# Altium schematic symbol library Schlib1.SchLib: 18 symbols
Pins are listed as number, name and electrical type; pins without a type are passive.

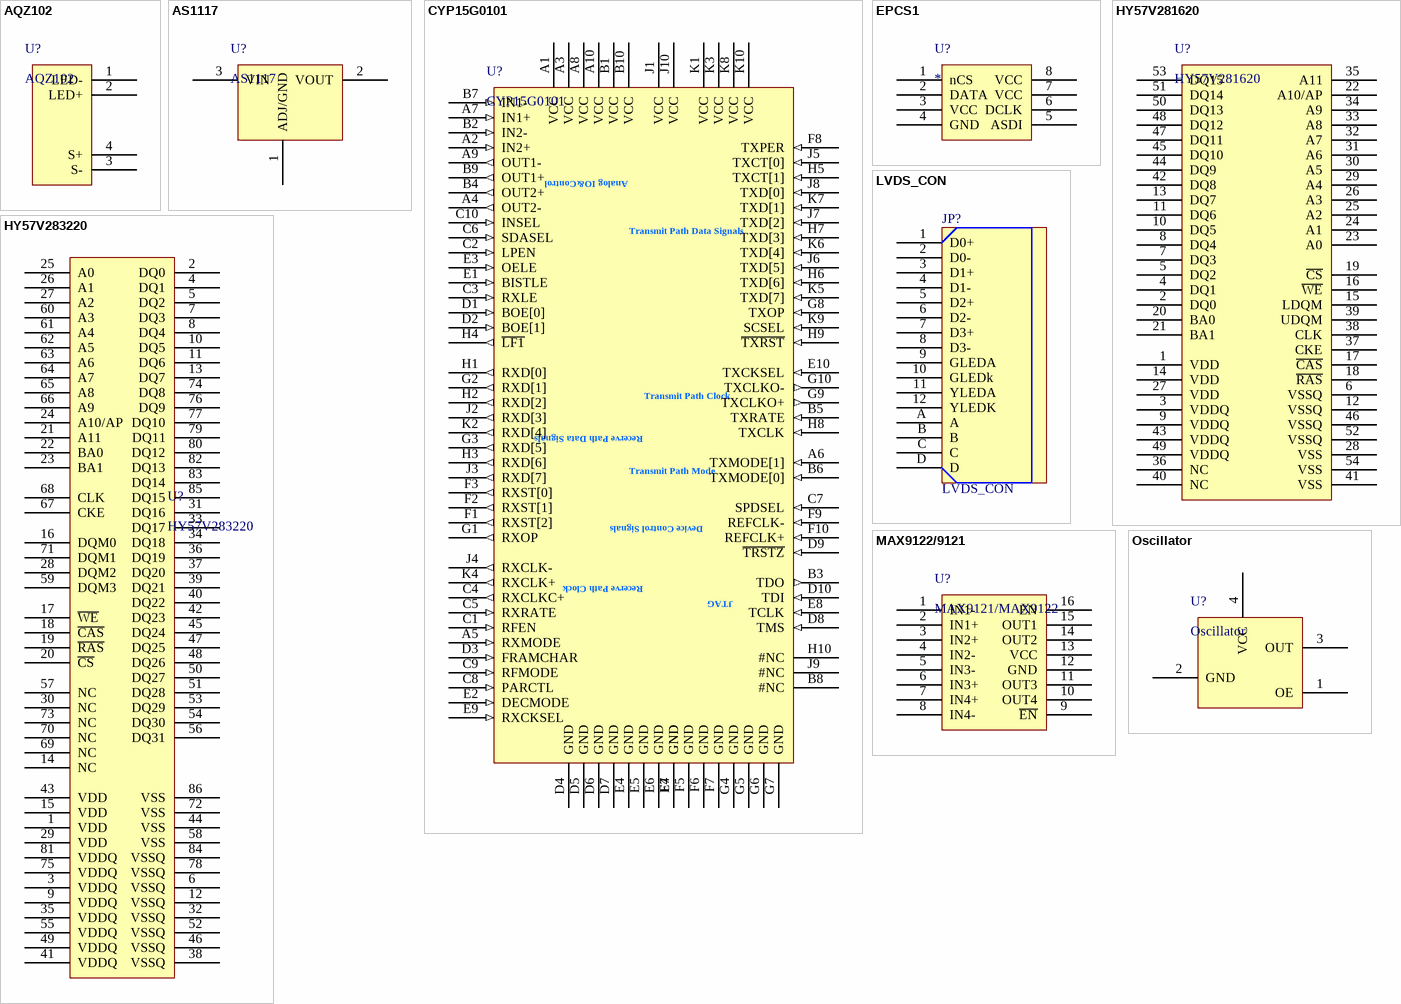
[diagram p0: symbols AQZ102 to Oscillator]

## AQZ102
designator U?
footprint AQZ102
pins: 1 LED-, 2 LED+, 3 S-, 4 S+

## AS1117
designator U?
footprint LM1117
pins: 1 ADJ/GND, 2 VOUT, 3 VIN

## CYP15G0101
designator U?
Hotlink II
footprint BGA100x10 (for CYP15G0101)
pins: A1 VCC, A2 IN2+ (in), A3 VCC, A4 OUT2- (out), A5 RXMODE (in), A6 TXMODE[1] (in), A7 IN1+ (in), A8 VCC, A9 OUT1- (out), A10 VCC, B1 VCC, B2 IN2- (in), B3 TDO (out), B4 OUT2+ (out), B5 TXRATE (in), B6 TXMODE[0] (in), B7 IN1- (in), B8 #NC, B9 OUT1+ (out), B10 VCC, C1 RFEN (in), C2 LPEN (in), C3 RXLE (in), C4 RXCLKC+ (out), C5 RXRATE (in), C6 SDASEL (in), C7 SPDSEL (in), C8 PARCTL (in), C9 RFMODE (in), C10 INSEL (in), D1 BOE[0] (in), D2 BOE[1] (in), D3 FRAMCHAR (in), D4 GND, D5 GND, D6 GND, D7 GND, D8 TMS (in), D9 ~{TRSTZ} (in), D10 TDI (in), E1 BISTLE (in), E2 DECMODE (in), E3 OELE (in), E4 GND, E5 GND, E6 GND, E7 GND, E8 TCLK (in), E9 RXCKSEL (in), E10 TXCKSEL (in), F1 RXST[2] (out), F2 RXST[1] (out), F3 RXST[0] (out), F4 GND, F5 GND, F6 GND, F7 GND, F8 TXPER (in), F9 REFCLK- (in), F10 REFCLK+ (in), G1 RXOP (out), G2 RXD[1] (out), G3 RXD[5] (out), G4 GND, G5 GND, G6 GND, G7 GND, G8 TXOP (in), G9 TXCLKO+ (out), G10 TXCLKO- (out), H1 RXD[0] (out), H2 RXD[2] (out), H3 RXD[6] (out), H4 ~{LF1} (out), H5 TXCT[1] (in), H6 TXD[6] (in), H7 TXD[3] (in), H8 TXCLK (in), H9 ~{TXRST} (in), H10 #NC, J1 VCC, J2 RXD[3] (out), J3 RXD[7] (out), J4 RXCLK- (out), J5 TXCT[0] (in), J6 TXD[5] (in), J7 TXD[2] (in), J8 TXD[0] (in), J9 #NC, J10 VCC, K1 VCC, K2 RXD[4] (out), K3 VCC, K4 RXCLK+ (out), K5 TXD[7] (in), K6 TXD[4] (in), K7 TXD[1] (in), K8 VCC, K9 SCSEL (in), K10 VCC

## EPCS1
designator U?
footprint Model Name (Footprint not found)
pins: 1 nCS, 2 DATA, 3 VCC, 4 GND, 5 ASDI, 6 DCLK, 7 VCC, 8 VCC

## HY57V281620
designator U?
footprint TSOP-54
pins: 1 VDD, 2 DQ0, 3 VDDQ, 4 DQ1, 5 DQ2, 6 VSSQ, 7 DQ3, 8 DQ4, 9 VDDQ, 10 DQ5, 11 DQ6, 12 VSSQ, 13 DQ7, 14 VDD, 15 LDQM, 16 ~{WE}, 17 ~{CAS}, 18 ~{RAS}, 19 ~{CS}, 20 BA0, 21 BA1, 22 A10/AP, 23 A0, 24 A1, 25 A2, 26 A3, 27 VDD, 28 VSS, 29 A4, 30 A5, 31 A6, 32 A7, 33 A8, 34 A9, 35 A11, 36 NC, 37 CKE, 38 CLK, 39 UDQM, 40 NC, 41 VSS, 42 DQ8, 43 VDDQ, 44 DQ9, 45 DQ10, 46 VSSQ, 47 DQ11, 48 DQ12, 49 VDDQ, 50 DQ13, 51 DQ14, 52 VSSQ, 53 DQ15, 54 VSS

## HY57V283220
designator U?
by TX
footprint TSOP86
pins: 1 VDD, 2 DQ0, 3 VDDQ, 4 DQ1, 5 DQ2, 6 VSSQ, 7 DQ3, 8 DQ4, 9 VDDQ, 10 DQ5, 11 DQ6, 12 VSSQ, 13 DQ7, 14 NC, 15 VDD, 16 DQM0, 17 ~{WE}, 18 ~{CAS}, 19 ~{RAS}, 20 ~{CS}, 21 A11, 22 BA0, 23 BA1, 24 A10/AP, 25 A0, 26 A1, 27 A2, 28 DQM2, 29 VDD, 30 NC, 31 DQ16, 32 VSSQ, 33 DQ17, 34 DQ18, 35 VDDQ, 36 DQ19, 37 DQ20, 38 VSSQ, 39 DQ21, 40 DQ22, 41 VDDQ, 42 DQ23, 43 VDD, 44 VSS, 45 DQ24, 46 VSSQ, 47 DQ25, 48 DQ26, 49 VDDQ, 50 DQ27, 51 DQ28, 52 VSSQ, 53 DQ29, 54 DQ30, 55 VDDQ, 56 DQ31, 57 NC, 58 VSS, 59 DQM3, 60 A3, 61 A4, 62 A5, 63 A6, 64 A7, 65 A8, 66 A9, 67 CKE, 68 CLK, 69 NC, 70 NC, 71 DQM1, 72 VSS, 73 NC, 74 DQ8, 75 VDDQ, 76 DQ9, 77 DQ10, 78 VSSQ, 79 DQ11, 80 DQ12, 81 VDDQ, 82 DQ13, 83 DQ14, 84 VSSQ, 85 DQ15, 86 VSS

## LVDS_CON
designator JP?
footprint HR911103A
pins: 1 D0+, 2 D0-, 3 D1+, 4 D1-, 5 D2+, 6 D2-, 7 D3+, 8 D3-, 9 GLEDA, 10 GLEDk, 11 YLEDA, 12 YLEDK, A, B, C, D

## MAX9122/9121
designator U?, comment MAX9121/MAX9122
footprint SOIC12 (for MAX9122/9121)
footprint SOP16 (for MAX9122)
pins: 1 IN1-, 2 IN1+, 3 IN2+, 4 IN2-, 5 IN3-, 6 IN3+, 7 IN4+, 8 IN4-, 9 ~{EN}, 10 OUT4, 11 OUT3, 12 GND, 13 VCC, 14 OUT2, 15 OUT1, 16 EN

## Oscillator
designator U?
footprint OSC50MHz (for 50MHz)
pins: 1 OE, 2 GND, 3 OUT, 4 VCC

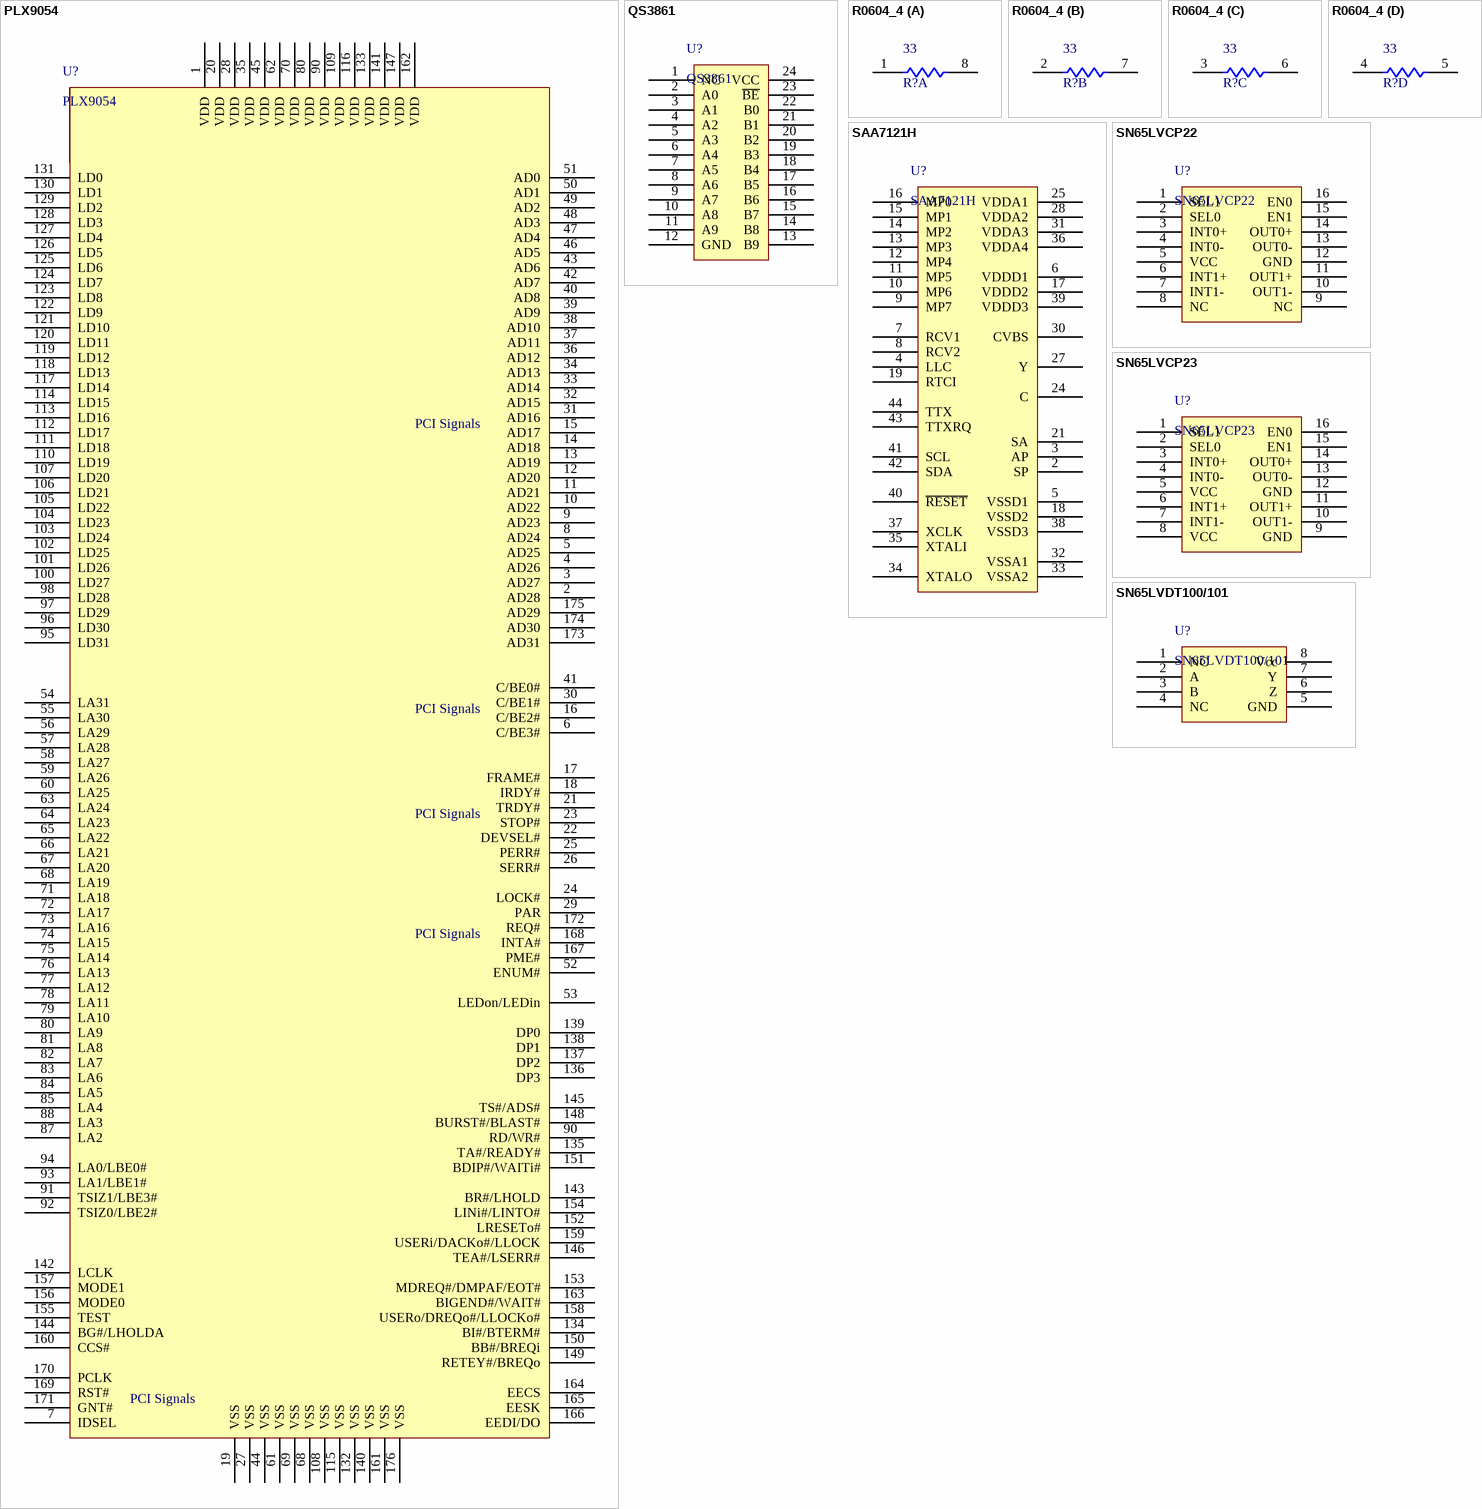
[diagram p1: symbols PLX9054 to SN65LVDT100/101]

## PLX9054
designator U?
footprint Quad176
pins: 1 VDD, 2 AD28, 3 AD27, 4 AD26, 5 AD25, 6 C/BE3#, 7 IDSEL, 8 AD24, 9 AD23, 10 AD22, 11 AD21, 12 AD20, 13 AD19, 14 AD18, 15 AD17, 16 C/BE2#, 17 FRAME#, 18 IRDY#, 19 VSS, 20 VDD, 21 TRDY#, 22 DEVSEL#, 23 STOP#, 24 LOCK#, 25 PERR#, 26 SERR#, 27 VSS, 28 VDD, 29 PAR, 30 C/BE1#, 31 AD16, 32 AD15, 33 AD14, 34 AD13, 35 VDD, 36 AD12, 37 AD11, 38 AD10, 39 AD9, 40 AD8, 41 C/BE0#, 42 AD7, 43 AD6, 44 VSS, 45 VDD, 46 AD5, 47 AD4, 48 AD3, 49 AD2, 50 AD1, 51 AD0, 52 ENUM#, 53 LEDon/LEDin, 54 LA31, 55 LA30, 56 LA29, 57 LA28, 58 LA27, 59 LA26, 60 LA25, 61 VSS, 62 VDD, 63 LA24, 64 LA23, 65 LA22, 66 LA21, 67 LA20, 68 VSS, 68 LA19, 69 VSS, 70 VDD, 71 LA18, 72 LA17, 73 LA16, 74 LA15, 75 LA14, 76 LA13, 77 LA12, 78 LA11, 79 LA10, 80 VDD, 80 LA9, 81 LA8, 82 LA7, 83 LA6, 84 LA5, 85 LA4, 87 LA2, 88 LA3, 90 VDD, 90 RD/WR#, 91 TSIZ1/LBE3#, 92 TSIZ0/LBE2#, 93 LA1/LBE1#, 94 LA0/LBE0#, 95 LD31, 96 LD30, 97 LD29, 98 LD28, 100 LD27, 101 LD26, 102 LD25, 103 LD24, 104 LD23, 105 LD22, 106 LD21, 107 LD20, 108 VSS, 109 VDD, 110 LD19, 111 LD18, 112 LD17, 113 LD16, 114 LD15, 115 VSS, 116 VDD, 117 LD14, 118 LD13, 119 LD12, 120 LD11, 121 LD10, 122 LD9, 123 LD8, 124 LD7, 125 LD6, 126 LD5, 127 LD4, 128 LD3, 129 LD2, 130 LD1, 131 LD0, 132 VSS, 133 VDD, 134 BI#/BTERM#, 135 TA#/READY#, 136 DP3, 137 DP2, 138 DP1, 139 DP0, 140 VSS, 141 VDD, 142 LCLK, 143 BR#/LHOLD, 144 BG#/LHOLDA, 145 TS#/ADS#, 146 TEA#/LSERR#, 147 VDD, 148 BURST#/BLAST#, 149 RETEY#/BREQo, 150 BB#/BREQi, 151 BDIP#/WAITi#, 152 LRESETo#, 153 MDREQ#/DMPAF/EOT#, 154 LINi#/LINTO#, 155 TEST, 156 MODE0, 157 MODE1, 158 USERo/DREQo#/LLOCKo#, 159 USERi/DACKo#/LLOCK, 160 CCS#, 161 VSS, 162 VDD, 163 BIGEND#/WAIT#, 164 EECS, 165 EESK, 166 EEDI/DO, 167 PME#, 168 INTA#, 169 RST#, 170 PCLK, 171 GNT#, 172 REQ#, 173 AD31, 174 AD30, 175 AD29, 176 VSS

## QS3861
designator U?
footprint TSSOP24 (for QS3861)
pins: 1 NC, 2 A0, 3 A1, 4 A2, 5 A3, 6 A4, 7 A5, 8 A6, 9 A7, 10 A8, 11 A9, 12 GND, 13 B9, 14 B8, 15 B7, 16 B6, 17 B5, 18 B4, 19 B3, 20 B2, 21 B1, 22 B0, 23 ~{BE}, 24 VCC

## R0604_4
designator R?  value 33
Resistor Array - Parts; Code - JEDEC: MS-012-AC; Code - IPC: SO16
footprint R0603_4 (for ResPackX4____OK!)
part A pins: 1, 8
part B pins: 2, 7
part C pins: 3, 6
part D pins: 4, 5

## SAA7121H
designator U?
footprint QFP44 (QFP44;for SAA7121H)
pins: 2 SP, 3 AP, 4 LLC, 5 VSSD1, 6 VDDD1, 7 RCV1, 8 RCV2, 9 MP7, 10 MP6, 11 MP5, 12 MP4, 13 MP3, 14 MP2, 15 MP1, 16 MP0, 17 VDDD2, 18 VSSD2, 19 RTCI, 21 SA, 24 C, 25 VDDA1, 27 Y, 28 VDDA2, 30 CVBS, 31 VDDA3, 32 VSSA1, 33 VSSA2, 34 XTALO, 35 XTALI, 36 VDDA4, 37 XCLK, 38 VSSD3, 39 VDDD3, 40 ~{RESET}, 41 SCL, 42 SDA, 43 TTXRQ, 44 TTX

## SN65LVCP22
designator U?
footprint Model Name (Model Description)
pins: 1 SEL1, 2 SEL0, 3 INT0+, 4 INT0-, 5 VCC, 6 INT1+, 7 INT1-, 8 NC, 9 NC, 10 OUT1-, 11 OUT1+, 12 GND, 13 OUT0-, 14 OUT0+, 15 EN1, 16 EN0

## SN65LVCP23
designator U?
pins: 1 SEL1, 2 SEL0, 3 INT0+, 4 INT0-, 5 VCC, 6 INT1+, 7 INT1-, 8 VCC, 9 GND, 10 OUT1-, 11 OUT1+, 12 GND, 13 OUT0-, 14 OUT0+, 15 EN1, 16 EN0

## SN65LVDT100/101
designator U?
footprint Model Name (Model Description)
pins: 1 NC, 2 A, 3 B, 4 NC, 5 GND, 6 Z, 7 Y, 8 Vcc

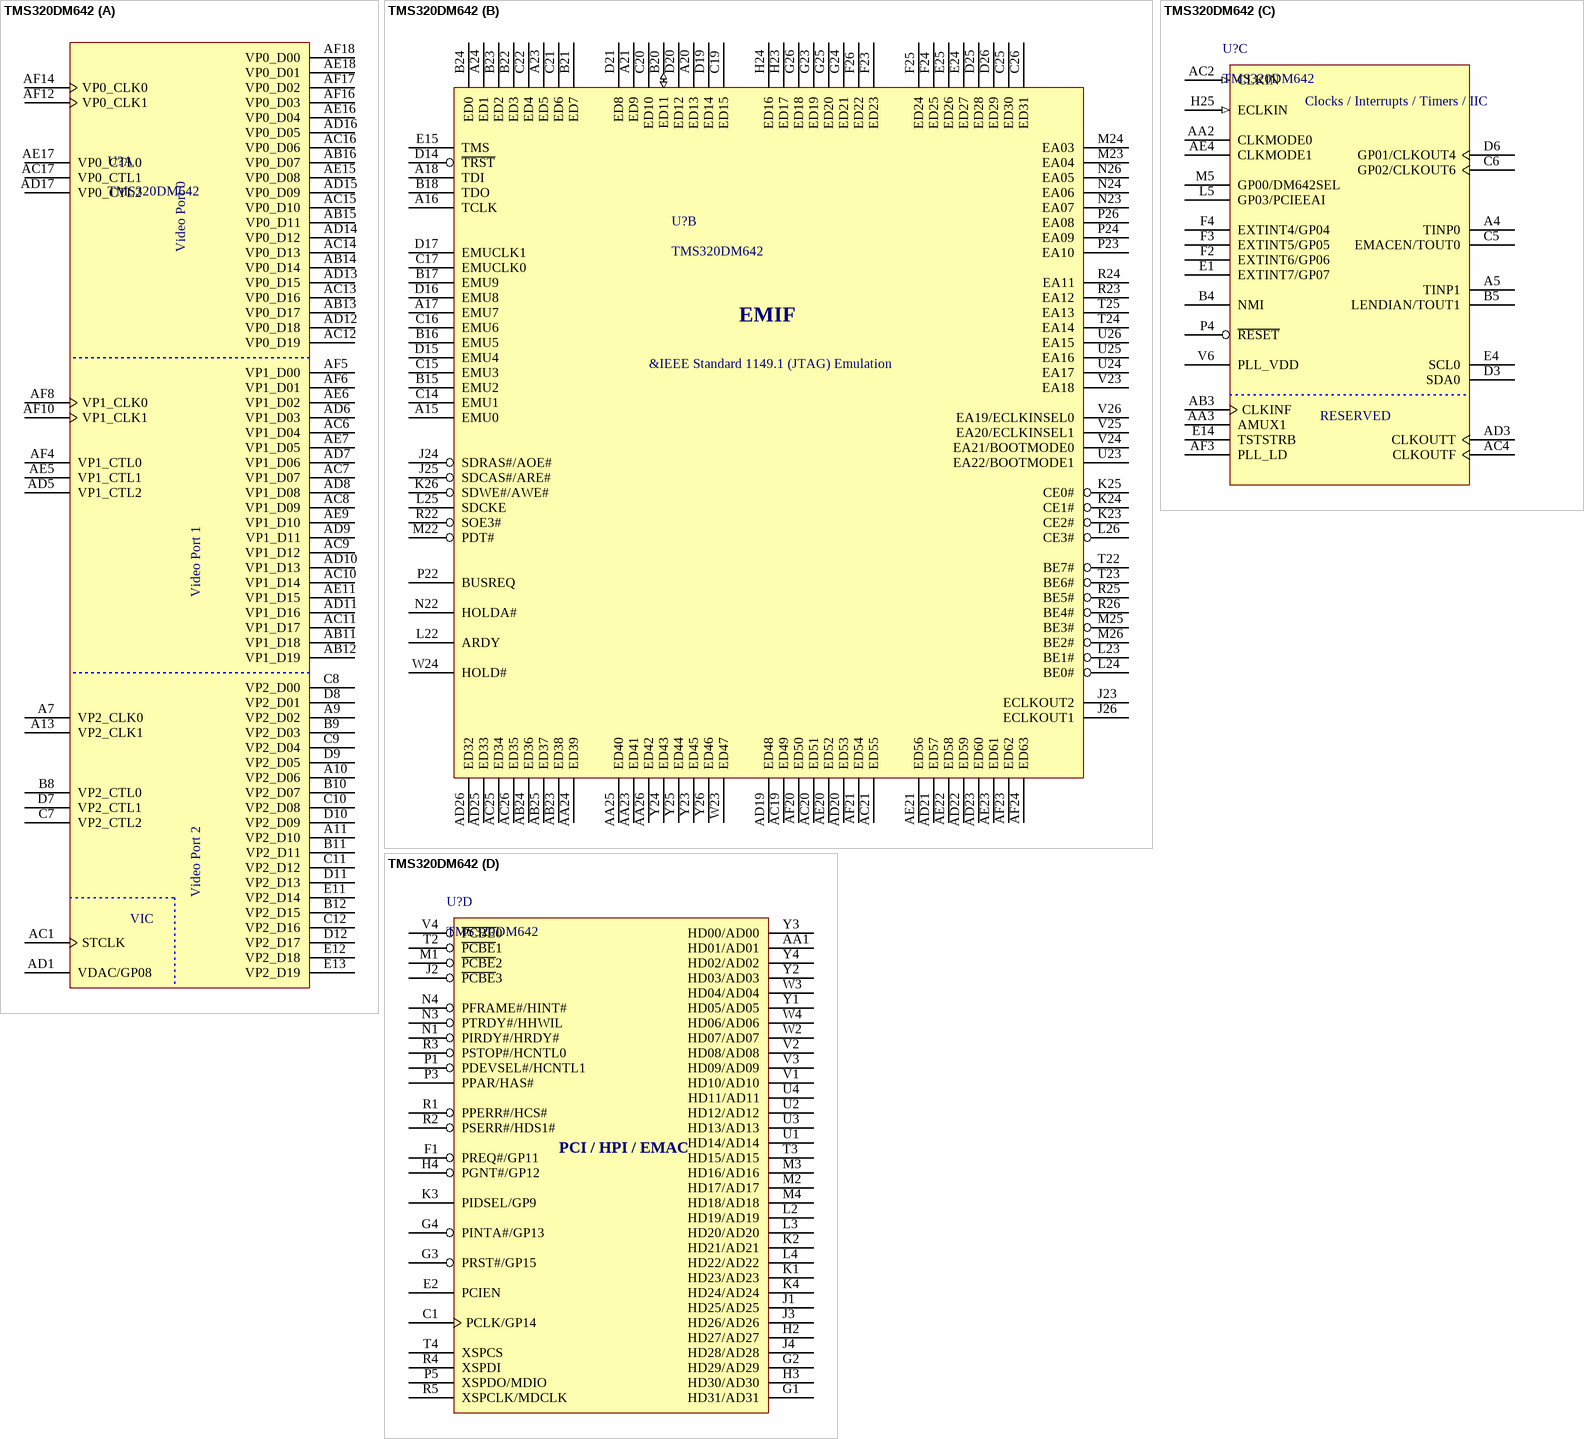
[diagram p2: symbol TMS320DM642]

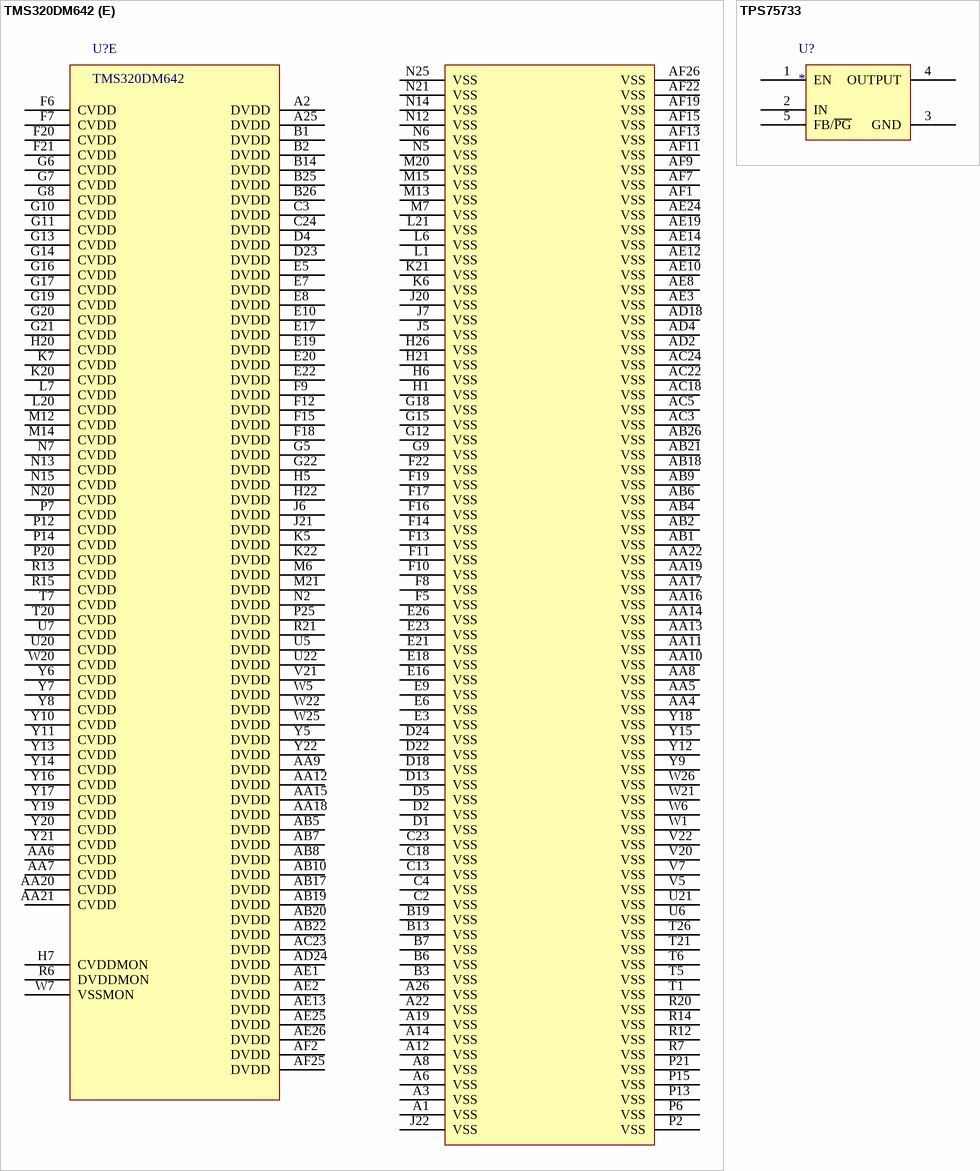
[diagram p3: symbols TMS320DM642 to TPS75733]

## TMS320DM642
designator U?
footprint GNZ548_1 (BGA;548 Balls;Body 27 x 27 mm;for DM642)
part A pins: A7 VP2_CLK0, A9 VP2_D02, A10 VP2_D06, A11 VP2_D10, A13 VP2_CLK1, AB11 VP1_D18, AB12 VP1_D19, AB13 VP0_D17, AB14 VP0_D14, AB15 VP0_D11, AB16 VP0_D07, AC1 STCLK, AC6 VP1_D04, AC7 VP1_D07, AC8 VP1_D09, AC9 VP1_D12, AC10 VP1_D14, AC11 VP1_D17, AC12 VP0_D19, AC13 VP0_D16, AC14 VP0_D13, AC15 VP0_D10, AC16 VP0_D06, AC17 VP0_CTL1, AD1 VDAC/GP08, AD5 VP1_CTL2, AD6 VP1_D03, AD7 VP1_D06, AD8 VP1_D08, AD9 VP1_D11, AD10 VP1_D13, AD11 VP1_D16, AD12 VP0_D18, AD13 VP0_D15, AD14 VP0_D12, AD15 VP0_D09, AD16 VP0_D05, AD17 VP0_CTL2, AE5 VP1_CTL1, AE6 VP1_D02, AE7 VP1_D05, AE9 VP1_D10, AE11 VP1_D15, AE15 VP0_D08, AE16 VP0_D04, AE17 VP0_CTL0, AE18 VP0_D01, AF4 VP1_CTL0, AF5 VP1_D00, AF6 VP1_D01, AF8 VP1_CLK0, AF10 VP1_CLK1, AF12 VP0_CLK1, AF14 VP0_CLK0, AF16 VP0_D03, AF17 VP0_D02, AF18 VP0_D00, B8 VP2_CTL0, B9 VP2_D03, B10 VP2_D07, B11 VP2_D11, B12 VP2_D15, C7 VP2_CTL2, C8 VP2_D00, C9 VP2_D04, C10 VP2_D08, C11 VP2_D12, C12 VP2_D16, D7 VP2_CTL1, D8 VP2_D01, D9 VP2_D05, D10 VP2_D09, D11 VP2_D13, D12 VP2_D17, E11 VP2_D14, E12 VP2_D18, E13 VP2_D19
part B pins: A15 EMU0, A16 TCLK, A17 EMU7, A18 TDI, A20 ED13, A21 ED9, A23 ED5, A24 ED1, AA23 ED41, AA24 ED39, AA25 ED40, AA26 ED42, AB23 ED38, AB24 ED36, AB25 ED37, AC19 ED49, AC20 ED51, AC21 ED55, AC25 ED34, AC26 ED35, AD19 ED48, AD20 ED53, AD21 ED57, AD22 ED59, AD23 ED60, AD25 ED33, AD26 ED32, AE20 ED52, AE21 ED56, AE22 ED58, AE23 ED61, AF20 ED50, AF21 ED54, AF23 ED62, AF24 ED63, B15 EMU2, B16 EMU5, B17 EMU9, B18 TDO, B20 ED11 (io), B21 ED7, B22 ED3, B23 ED2, B24 ED0, C14 EMU1, C15 EMU3, C16 EMU6, C17 EMUCLK0, C19 ED15, C20 ED10, C21 ED6, C22 ED4, C25 ED30, C26 ED31, D14 ~{TRST}, D15 EMU4, D16 EMU8, D17 EMUCLK1, D19 ED14, D20 ED12, D21 ED8, D25 ED28, D26 ED29, E15 TMS, E24 ED27, E25 ED26, F23 ED23, F24 ED25, F25 ED24, F26 ED22, G23 ED19, G24 ED21, G25 ED20, G26 ED18, H23 ED17, H24 ED16, J23 ECLKOUT2, J24 SDRAS#/AOE#, J25 SDCAS#/ARE#, J26 ECLKOUT1, K23 CE2#, K24 CE1#, K25 CE0#, K26 SDWE#/AWE#, L22 ARDY, L23 BE1#, L24 BE0#, L25 SDCKE, L26 CE3#, M22 PDT#, M23 EA04, M24 EA03, M25 BE3#, M26 BE2#, N22 HOLDA#, N23 EA07, N24 EA06, N26 EA05, P22 BUSREQ, P23 EA10, P24 EA09, P26 EA08, R22 SOE3#, R23 EA12, R24 EA11, R25 BE5#, R26 BE4#, T22 BE7#, T23 BE6#, T24 EA14, T25 EA13, U23 EA22/BOOTMODE1, U24 EA17, U25 EA16, U26 EA15, V23 EA18, V24 EA21/BOOTMODE0, V25 EA20/ECLKINSEL1, V26 EA19/ECLKINSEL0, W23 ED47, W24 HOLD#, Y23 ED45, Y24 ED43, Y25 ED44, Y26 ED46
part C pins: A4 TINP0, A5 TINP1, AA2 CLKMODE0, AA3 AMUX1, AB3 CLKINF, AC2 CLKIN (in), AC4 CLKOUTF, AD3 CLKOUTT, AE4 CLKMODE1, AF3 PLL_LD, B4 NMI, B5 LENDIAN/TOUT1, C5 EMACEN/TOUT0, C6 GP02/CLKOUT6, D3 SDA0, D6 GP01/CLKOUT4, E1 EXTINT7/GP07, E4 SCL0, E14 TSTSTRB, F2 EXTINT6/GP06, F3 EXTINT5/GP05, F4 EXTINT4/GP04, H25 ECLKIN (in), L5 GP03/PCIEEAI, M5 GP00/DM642SEL, P4 ~{RESET}, V6 PLL_VDD
part D pins: AA1 HD01/AD01, C1 PCLK/GP14, E2 PCIEN, F1 PREQ#/GP11, G1 HD31/AD31, G2 HD29/AD29, G3 PRST#/GP15, G4 PINTA#/GP13, H2 HD27/AD27, H3 HD30/AD30, H4 PGNT#/GP12, J1 HD25/AD25, J2 ~{PCBE}3, J3 HD26/AD26, J4 HD28/AD28, K1 HD23/AD23, K2 HD21/AD21, K3 PIDSEL/GP9, K4 HD24/AD24, L2 HD19/AD19, L3 HD20/AD20, L4 HD22/AD22, M1 ~{PCBE}2, M2 HD17/AD17, M3 HD16/AD16, M4 HD18/AD18, N1 PIRDY#/HRDY#, N3 PTRDY#/HHWIL, N4 PFRAME#/HINT#, P1 PDEVSEL#/HCNTL1, P3 PPAR/HAS#, P5 XSPDO/MDIO, R1 PPERR#/HCS#, R2 PSERR#/HDS1#, R3 PSTOP#/HCNTL0, R4 XSPDI, R5 XSPCLK/MDCLK, T2 ~{PCBE}1, T3 HD15/AD15, T4 XSPCS, U1 HD14/AD14, U2 HD12/AD12, U3 HD13/AD13, U4 HD11/AD11, V1 HD10/AD10, V2 HD08/AD08, V3 HD09/AD09, V4 ~{PCBE}0, W2 HD07/AD07, W3 HD04/AD04, W4 HD06/AD06, Y1 HD05/AD05, Y2 HD03/AD03, Y3 HD00/AD00, Y4 HD02/AD02
part E pins: A1 VSS (power), A2 DVDD (power), A3 VSS (power), A6 VSS (power), A8 VSS (power), A12 VSS (power), A14 VSS (power), A19 VSS (power), A22 VSS (power), A25 DVDD (power), A26 VSS (power), AA4 VSS (power), AA5 VSS (power), AA6 CVDD (power), AA7 CVDD (power), AA8 VSS (power), AA9 DVDD (power), AA10 VSS (power), AA11 VSS (power), AA12 DVDD (power), AA13 VSS (power), AA14 VSS (power), AA15 DVDD (power), AA16 VSS (power), AA17 VSS (power), AA18 DVDD (power), AA19 VSS (power), AA20 CVDD (power), AA21 CVDD (power), AA22 VSS (power), AB1 VSS (power), AB2 VSS (power), AB4 VSS (power), AB5 DVDD (power), AB6 VSS (power), AB7 DVDD (power), AB8 DVDD (power), AB9 VSS (power), AB10 DVDD (power), AB17 DVDD (power), AB18 VSS (power), AB19 DVDD (power), AB20 DVDD (power), AB21 VSS (power), AB22 DVDD (power), AB26 VSS (power), AC3 VSS (power), AC5 VSS (power), AC18 VSS (power), AC22 VSS (power), AC23 DVDD (power), AC24 VSS (power), AD2 VSS (power), AD4 VSS (power), AD18 VSS (power), AD24 DVDD (power), AE1 DVDD (power), AE2 DVDD (power), AE3 VSS (power), AE8 VSS (power), AE10 VSS (power), AE12 VSS (power), AE13 DVDD (power), AE14 VSS (power), AE19 VSS (power), AE24 VSS (power), AE25 DVDD (power), AE26 DVDD (power), AF1 VSS (power), AF2 DVDD (power), AF7 VSS (power), AF9 VSS (power), AF11 VSS (power), AF13 VSS (power), AF15 VSS (power), AF19 VSS (power), AF22 VSS (power), AF25 DVDD (power), AF26 VSS (power), B1 DVDD (power), B2 DVDD (power), B3 VSS (power), B6 VSS (power), B7 VSS (power), B13 VSS (power), B14 DVDD (power), B19 VSS (power), B25 DVDD (power), B26 DVDD (power), C2 VSS (power), C3 DVDD (power), C4 VSS (power), C13 VSS (power), C18 VSS (power), C23 VSS (power), C24 DVDD (power), D1 VSS (power), D2 VSS (power), D4 DVDD (power), D5 VSS (power), D13 VSS (power), D18 VSS (power), D22 VSS (power), D23 DVDD (power), D24 VSS (power), E3 VSS (power), E5 DVDD (power), E6 VSS (power), E7 DVDD (power), E8 DVDD (power), E9 VSS (power), E10 DVDD (power), E16 VSS (power), E17 DVDD (power), E18 VSS (power), E19 DVDD (power), E20 DVDD (power), E21 VSS (power), E22 DVDD (power), E23 VSS (power), E26 VSS (power), F5 VSS (power), F6 CVDD (power), F7 CVDD (power), F8 VSS (power), F9 DVDD (power), F10 VSS (power), F11 VSS (power), F12 DVDD (power), F13 VSS (power), F14 VSS (power), F15 DVDD (power), F16 VSS (power), F17 VSS (power), F18 DVDD (power), F19 VSS (power), F20 CVDD (power), F21 CVDD (power), F22 VSS (power), G5 DVDD (power), G6 CVDD (power), G7 CVDD (power), G8 CVDD (power), G9 VSS (power), G10 CVDD (power), G11 CVDD (power), G12 VSS (power), G13 CVDD (power), G14 CVDD (power), G15 VSS (power), G16 CVDD (power), G17 CVDD (power), G18 VSS (power), G19 CVDD (power), G20 CVDD (power), G21 CVDD (power), G22 DVDD (power), H1 VSS (power), H5 DVDD (power), H6 VSS (power), H7 CVDDMON (power), H20 CVDD (power), H21 VSS (power), H22 DVDD (power), H26 VSS (power), J5 VSS (power), J6 DVDD (power), J7 VSS (power), J20 VSS (power), J21 DVDD (power), J22 VSS (power), K5 DVDD (power), K6 VSS (power), K7 CVDD (power), K20 CVDD (power), K21 VSS (power), K22 DVDD (power), L1 VSS (power), L6 VSS (power), L7 CVDD (power), L20 CVDD (power), L21 VSS (power), M6 DVDD (power), M7 VSS (power), M12 CVDD (power), M13 VSS (power), M14 CVDD (power), M15 VSS (power), M20 VSS (power), M21 DVDD (power), N2 DVDD (power), N5 VSS (power), N6 VSS (power), N7 CVDD (power), N12 VSS (power), N13 CVDD (power), N14 VSS (power), N15 CVDD (power), N20 CVDD (power), N21 VSS (power), N25 VSS (power), P2 VSS (power), P6 VSS (power), P7 CVDD (power), P12 CVDD (power), P13 VSS (power), P14 CVDD (power), P15 VSS (power), P20 CVDD (power), P21 VSS (power), P25 DVDD (power), R6 DVDDMON (power), R7 VSS (power), R12 VSS (power), R13 CVDD (power), R14 VSS (power), R15 CVDD (power), R20 VSS (power), R21 DVDD (power), T1 VSS (power), T5 VSS (power), T6 VSS (power), T7 CVDD (power), T20 CVDD (power), T21 VSS (power), T26 VSS (power), U5 DVDD (power), U6 VSS (power), U7 CVDD (power), U20 CVDD (power), U21 VSS (power), U22 DVDD (power), V5 VSS (power), V7 VSS (power), V20 VSS (power), V21 DVDD (power), V22 VSS (power), W1 VSS (power), W5 DVDD (power), W6 VSS (power), W7 VSSMON (power), W20 CVDD (power), W21 VSS (power), W22 DVDD (power), W25 DVDD (power), W26 VSS (power), Y5 DVDD (power), Y6 CVDD (power), Y7 CVDD (power), Y8 CVDD (power), Y9 VSS (power), Y10 CVDD (power), Y11 CVDD (power), Y12 VSS (power), Y13 CVDD (power), Y14 CVDD (power), Y15 VSS (power), Y16 CVDD (power), Y17 CVDD (power), Y18 VSS (power), Y19 CVDD (power), Y20 CVDD (power), Y21 CVDD (power), Y22 DVDD (power)

## TPS75733
designator U?
pins: 1 EN (oc), 2 IN (oc), 3 GND (oc), 4 OUTPUT (oc), 5 FB/~{PG} (oc)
